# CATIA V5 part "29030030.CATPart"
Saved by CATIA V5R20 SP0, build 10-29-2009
Part number: 29030030
Definition: NONE
Nomenclature: 29030030
Source: Unknown
Description: 29030030
Bounding box of the stored display mesh (mm): x -15 to 44.548, y -29 to 63.548, z -19 to 19
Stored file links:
  C:\Users\Utente\Desktop\IO LAVORO\3D X SITO CF\X SITO\PLASTICA\RF1\29030030.CATPart
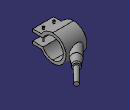
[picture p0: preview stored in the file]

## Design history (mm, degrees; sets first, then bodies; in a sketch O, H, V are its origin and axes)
Body1 "29030030" (main body)
  Solid1: solid without history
